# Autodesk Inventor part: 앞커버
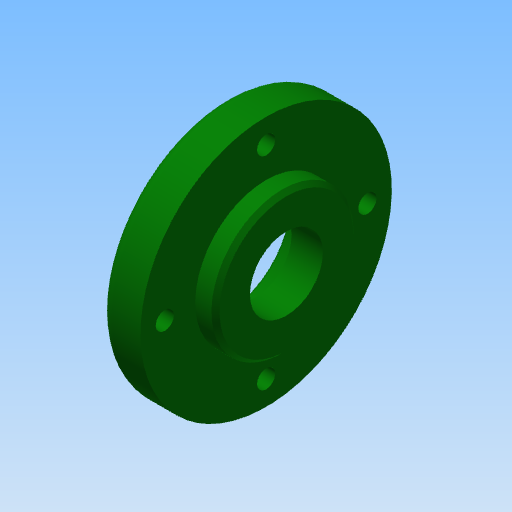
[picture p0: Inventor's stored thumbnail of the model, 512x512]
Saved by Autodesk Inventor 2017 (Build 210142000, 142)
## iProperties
Created: 2015-12
Part Number: 앞커버
Document SubType Name: Modeling
Designer: mdu
Density: 2.71 g/cm^3
Material: 알루미늄 6061
Appearance: 진녹색
Mass: 70.9292 g
Surface Area: 93.9278 cm^2
Volume: 26.1731 cm^3
Author: mdu
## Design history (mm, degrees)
sketch "스케치1"
  geometry: L1 (-7.5, 0)-(7.5, 0); L2 (-7.5, 0)-(-7.5, 31); L3 (-7.5, 31)-(2.5, 31); L4 (2.5, 31)-(2.5, 17.5); L5 (2.5, 17.5)-(7.5, 17.5); L6 (7.5, 17.5)-(7.5, 0); 2 further points
  constraints: 12 end point, 3 perpendicular, 1 coincident, 1 horizontal, 1 midpoint, 1 parallel
  dimensions: "d0" = 15 distance of L1.start L1.end; "d1" = 62 diameter of L3 L1; "d2" = 35 diameter of L5 L1; "d5" = 10 distance of L2.end L3.end
revolve "회전1" sketch "스케치1" stored, may be unused: angle "d6" = 90 deg
sketch "스케치2" dims "d42" = 50
  geometry: 3 further points
  constraints: 2 vertical alignment, 1 coincident, 2 other
hole "구멍1" sketch "스케치2" at (0, 25) diameter "d8" = 4.5; stored, may be unused: countersink angle "d12" = 90 deg, drill point angle "d14" = 118 deg; dims "d9" = 6, "d10" = 8, "d11" = 4.4, "d13" = 8
hole "구멍2" diameter "d20" = 18; stored, may be unused: countersink angle "d24" = 90 deg, drill point angle "d26" = 0 deg; dims "d18" = 10, "d19" = 10, "d21" = 6, "d22" = 8, "d23" = 4.4, "d25" = 8
hole "구멍3" diameter "d34" = 30; stored, may be unused: countersink angle "d38" = 90 deg, drill point angle "d40" = 0 deg; dims "d32" = 10, "d33" = 10, "d35" = 6, "d36" = 4, "d37" = 2, "d39" = 7.3
fillet "모깎기1" dims "d27" = 3, "d41" = 0.3
chamfer "모따기1" distance "d29" = 1; stored, may be unused: second distance "d30" = 2, angle "d31" = 45 deg
node "솔리드1"
pattern_circular "원형 패턴1" dims angle "d16" = 360 deg
